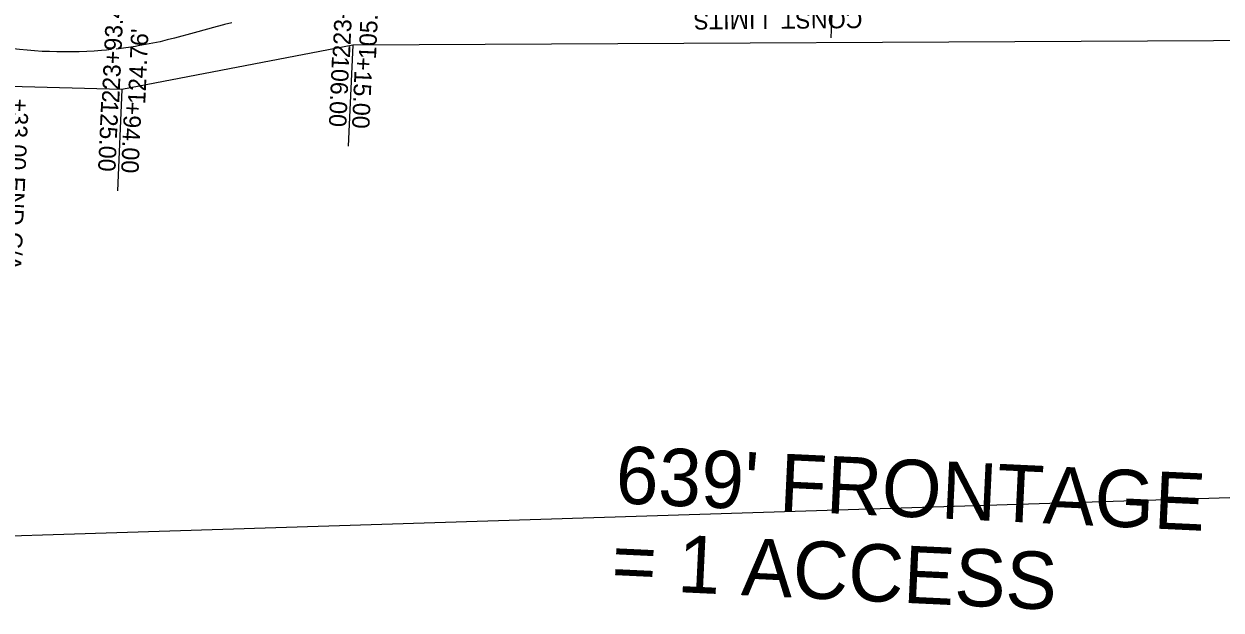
# Model space of a CAD drawing. Extents: x -70 to 701944, y -4 to 666871.
# Drawn here: x 665760.5 to 666174.3, y 656341.8 to 656544.4 of the extents above; entities that cross this region are included whole.
import ezdxf

# ---------------------------------------------------------------- set-up
doc = ezdxf.new("R2010")
doc.units = 0
for name, color, linetype in [('R_Detour', 7, 'Continuous'), ('R_No Plot', 7, 'Continuous'), ('R_Proposed Const Limits', 7, 'Continuous'), ('R_ROW', 7, 'Continuous'), ('R_Temp Easement Annot', 7, 'Continuous')]:
    doc.layers.add(name, color=color, linetype=linetype)

msp = doc.modelspace()

# ---------------------------------------------------------------- linework, layer by layer
at = {"layer": 'R_Detour'}
msp.add_line((666039.46, 656539.6), (666043.8, 656635.59), dxfattribs=at)
msp.add_lwpolyline([(666737.89, 656398.26), (665345.58, 656354.44), (665419.48, 656455.77)], dxfattribs=at)
at = {"layer": 'R_Proposed Const Limits'}
for points in [[(665832.37, 656544.82), (665829.84, 656544.21), (665829.45, 656544.11), (665827.31, 656543.56), (665819.31, 656541.36), (665812.52, 656539.53), (665810.04, 656538.9), (665809.18, 656538.69), (665807.55, 656538.31), (665805.06, 656537.77), (665802.55, 656537.28), (665800.04, 656536.83), (665799.08, 656536.67), (665797.51, 656536.43), (665794.98, 656536.07), (665792.44, 656535.73)], [(665790.83, 656535.56), (665789.89, 656535.47), (665789.01, 656535.38), (665787.34, 656535.23), (665784.78, 656535.04), (665782.22, 656534.9), (665779.65, 656534.8), (665778.98, 656534.78), (665777.08, 656534.75), (665774.51, 656534.75), (665771.93, 656534.79), (665769.36, 656534.87), (665768.97, 656534.89), (665767.82, 656534.92), (665766.78, 656534.97), (665764.2, 656535.14), (665761.63, 656535.35), (665759.05, 656535.61), (665758.99, 656535.61), (665749.03, 656536.69), (665739.07, 656537.76), (665729.11, 656538.83), (665719.15, 656539.9)]]:
    msp.add_lwpolyline(points, dxfattribs=at)
at = {"layer": 'R_ROW'}
msp.add_lwpolyline([(668068.22, 656367.07), (668015.2, 656409.61), (667518.06, 656430.84), (667204.93, 656412.96), (667078.78, 656456.7), (667035.95, 656483.66), (666996.35, 656493.45), (666927.34, 656472.55), (666845.47, 656477.25), (666774.58, 656503.47), (666573.01, 656517.59), (666494.28, 656503.13), (666386.7, 656514.99), (666322.44, 656532.91), (666194.58, 656538.69), (665874.18, 656537.15), (665794.4, 656521.73), (665682.43, 656524.79)], dxfattribs=at)
at = {"layer": 'R_Temp Easement Annot'}
for points in [[(665874.18, 656537.15), (665872.6, 656502.18)], [(665794.4, 656521.73), (665792.82, 656486.77)]]:
    msp.add_lwpolyline(points, dxfattribs=at)

# ---------------------------------------------------------------- texts
at = {"layer": 'R_No Plot'}
for s, height, rotation, p in [('223+14.52 ', 6, 87.4131, (665873.18, 656532.59)), ("105.61' ", 6, 87.4131, (665882.17, 656532.18)), ('223+93.47 ', 6, 87.4131, (665793.44, 656517.01)), ("124.76' ", 6, 87.4131, (665802.43, 656516.61)), ("639' FRONTAGE ", 19.8226, 357.2978, (665964.72, 656378.77)), ('= 1 ACCESS', 19.823, 357.2978, (665963.32, 656349.07))]:
    msp.add_text(s, height=height, rotation=rotation, dxfattribs=at).set_placement(p)
at = {"layer": 'R_Proposed Const Limits'}
msp.add_text('CONST. LIMITS', height=6, rotation=180.5133, dxfattribs=at).set_placement((666050.3, 656549.02))
at = {"layer": 'R_Temp Easement Annot'}
for s, p in [('106.00', (665867.01, 656533.47)), ('+15.00', (665875, 656533.11)), ('+33.00 END C/A', (665756.23, 656518.76)), ('125.00', (665787.23, 656518.05)), ('+94.00', (665795.22, 656517.69))]:
    msp.add_text(s, height=6, rotation=267.4131, dxfattribs=at).set_placement(p)

doc.saveas('drawing.dxf')
